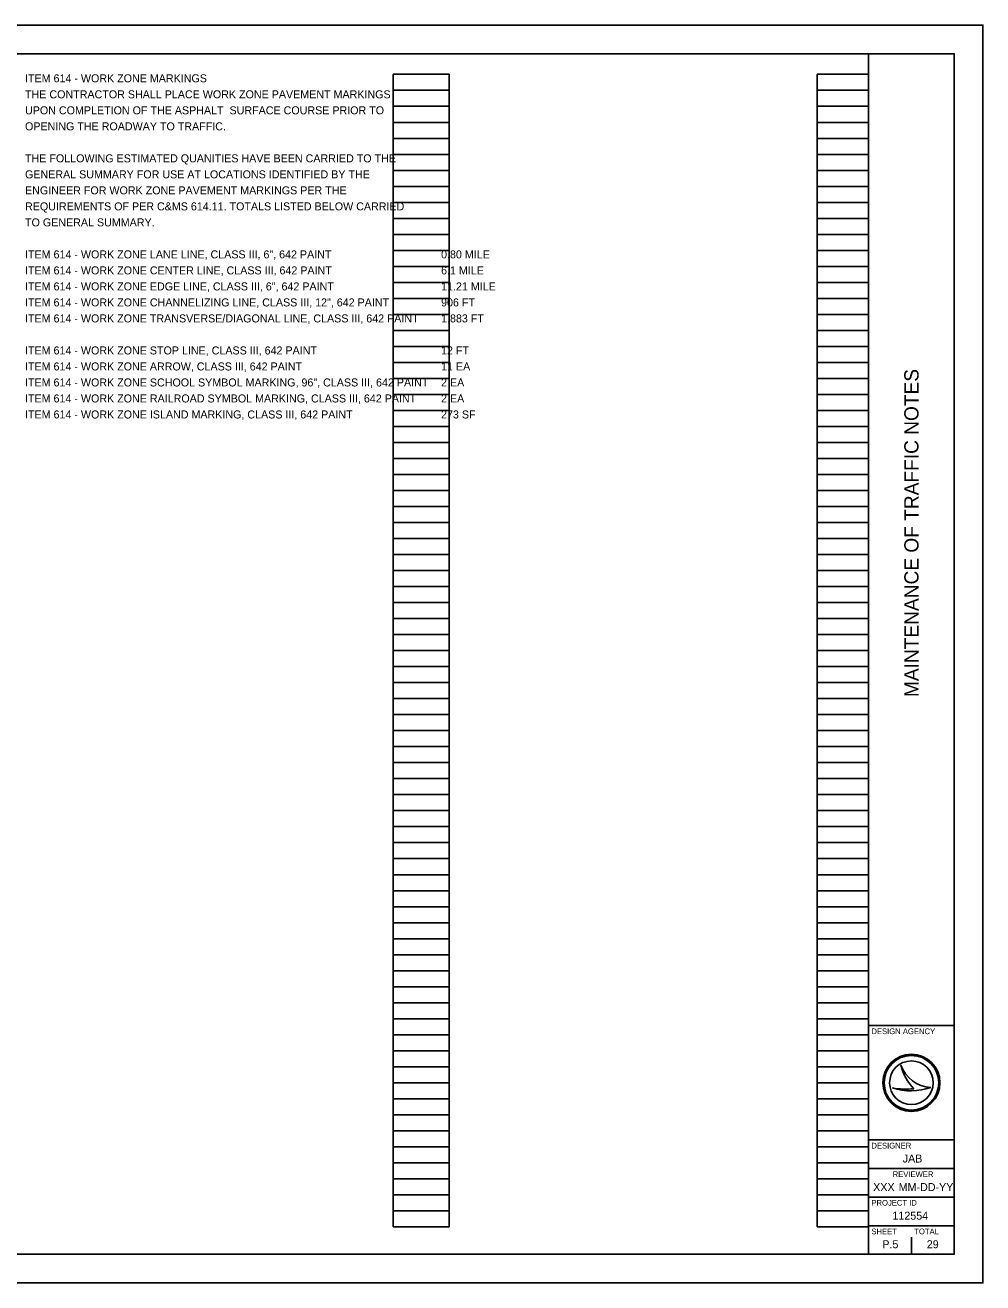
# Model space of a CAD drawing. Extents: x 0 to 34, y 0 to 22.
# Drawn here: x 17.24 to 34, y 0 to 22 of the extents above; entities that cross this region are included whole.
import ezdxf

# ---------------------------------------------------------------- set-up
doc = ezdxf.new("R2010")
doc.units = 0
for name, color, linetype in [('SH_Border', 7, 'Continuous'), ('SH_Cut_Line', 7, 'Continuous'), ('SH_Data', 7, 'Continuous'), ('SH_Text', 7, 'Continuous')]:
    doc.layers.add(name, color=color, linetype=linetype)

msp = doc.modelspace()

# ---------------------------------------------------------------- linework, layer by layer
at = {"layer": 'SH_Border'}
for p, q in [((32, 0.5), (32, 21.5)), ((32, 4.5), (33.5, 4.5)), ((32, 2.5), (33.5, 2.5)), ((32, 2), (33.5, 2)), ((32, 1.5), (33.5, 1.5)), ((32, 1), (33.5, 1))]:
    msp.add_line(p, q, dxfattribs=at)
msp.add_lwpolyline([(1.5, 21.5), (33.5, 21.5), (33.5, 0.5), (1.5, 0.5)], close=True, dxfattribs=at)
at = {"layer": 'SH_Cut_Line'}
msp.add_lwpolyline([(0, 0), (34, 0), (34, 22), (0, 22)], close=True, dxfattribs=at)
at = {"layer": 'SH_Data'}
for p, q in [((23.68, 0.98), (23.68, 21.14)), ((23.68, 21.14), (24.66, 21.14)), ((24.66, 0.98), (24.66, 21.14)), ((31.1, 0.98), (31.1, 21.14)), ((31.1, 21.14), (32, 21.14)), ((32, 0.98), (32, 21.14)), ((23.68, 20.86), (24.66, 20.86)), ((31.1, 20.86), (32, 20.86)), ((23.68, 20.58), (24.66, 20.58)), ((31.1, 20.58), (32, 20.58)), ((23.68, 20.3), (24.66, 20.3)), ((31.1, 20.3), (32, 20.3)), ((23.68, 20.02), (24.66, 20.02)), ((31.1, 20.02), (32, 20.02)), ((23.68, 19.74), (24.66, 19.74)), ((31.1, 19.74), (32, 19.74)), ((23.68, 19.46), (24.66, 19.46)), ((31.1, 19.46), (32, 19.46)), ((23.68, 19.18), (24.66, 19.18)), ((31.1, 19.18), (32, 19.18)), ((23.68, 18.9), (24.66, 18.9)), ((31.1, 18.9), (32, 18.9)), ((23.68, 18.62), (24.66, 18.62)), ((31.1, 18.62), (32, 18.62)), ((23.68, 18.34), (24.66, 18.34)), ((31.1, 18.34), (32, 18.34)), ((23.68, 18.06), (24.66, 18.06)), ((31.1, 18.06), (32, 18.06)), ((23.68, 17.78), (24.66, 17.78)), ((31.1, 17.78), (32, 17.78)), ((23.68, 17.5), (24.66, 17.5)), ((31.1, 17.5), (32, 17.5)), ((23.68, 17.22), (24.66, 17.22)), ((31.1, 17.22), (32, 17.22)), ((23.68, 16.94), (24.66, 16.94)), ((31.1, 16.94), (32, 16.94)), ((23.68, 16.66), (24.66, 16.66)), ((31.1, 16.66), (32, 16.66)), ((23.68, 16.38), (24.66, 16.38)), ((31.1, 16.38), (32, 16.38)), ((23.68, 16.1), (24.66, 16.1)), ((31.1, 16.1), (32, 16.1)), ((23.68, 15.82), (24.66, 15.82)), ((31.1, 15.82), (32, 15.82)), ((23.68, 15.54), (24.66, 15.54)), ((31.1, 15.54), (32, 15.54)), ((23.68, 15.26), (24.66, 15.26)), ((31.1, 15.26), (32, 15.26)), ((23.68, 14.98), (24.66, 14.98)), ((31.1, 14.98), (32, 14.98)), ((23.68, 14.7), (24.66, 14.7)), ((31.1, 14.7), (32, 14.7)), ((23.68, 14.42), (24.66, 14.42)), ((31.1, 14.42), (32, 14.42)), ((23.68, 14.14), (24.66, 14.14)), ((31.1, 14.14), (32, 14.14)), ((23.68, 13.86), (24.66, 13.86)), ((31.1, 13.86), (32, 13.86)), ((23.68, 13.58), (24.66, 13.58)), ((31.1, 13.58), (32, 13.58)), ((23.68, 13.3), (24.66, 13.3)), ((31.1, 13.3), (32, 13.3)), ((23.68, 13.02), (24.66, 13.02)), ((31.1, 13.02), (32, 13.02)), ((23.68, 12.74), (24.66, 12.74)), ((31.1, 12.74), (32, 12.74)), ((23.68, 12.46), (24.66, 12.46)), ((31.1, 12.46), (32, 12.46)), ((23.68, 12.18), (24.66, 12.18)), ((31.1, 12.18), (32, 12.18)), ((23.68, 11.9), (24.66, 11.9)), ((31.1, 11.9), (32, 11.9)), ((23.68, 11.62), (24.66, 11.62)), ((31.1, 11.62), (32, 11.62)), ((23.68, 11.34), (24.66, 11.34)), ((31.1, 11.34), (32, 11.34)), ((23.68, 11.06), (24.66, 11.06)), ((31.1, 11.06), (32, 11.06)), ((23.68, 10.78), (24.66, 10.78)), ((31.1, 10.78), (32, 10.78)), ((23.68, 10.5), (24.66, 10.5)), ((31.1, 10.5), (32, 10.5)), ((23.68, 10.22), (24.66, 10.22)), ((31.1, 10.22), (32, 10.22)), ((23.68, 9.94), (24.66, 9.94)), ((31.1, 9.94), (32, 9.94)), ((23.68, 9.66), (24.66, 9.66)), ((31.1, 9.66), (32, 9.66)), ((23.68, 9.38), (24.66, 9.38)), ((31.1, 9.38), (32, 9.38)), ((23.68, 9.1), (24.66, 9.1)), ((31.1, 9.1), (32, 9.1)), ((23.68, 8.82), (24.66, 8.82)), ((31.1, 8.82), (32, 8.82)), ((23.68, 8.54), (24.66, 8.54)), ((31.1, 8.54), (32, 8.54)), ((23.68, 8.26), (24.66, 8.26)), ((31.1, 8.26), (32, 8.26)), ((23.68, 7.98), (24.66, 7.98)), ((31.1, 7.98), (32, 7.98)), ((23.68, 7.7), (24.66, 7.7)), ((31.1, 7.7), (32, 7.7)), ((23.68, 7.42), (24.66, 7.42)), ((31.1, 7.42), (32, 7.42)), ((23.68, 7.14), (24.66, 7.14)), ((31.1, 7.14), (32, 7.14)), ((23.68, 6.86), (24.66, 6.86)), ((31.1, 6.86), (32, 6.86)), ((23.68, 6.58), (24.66, 6.58)), ((31.1, 6.58), (32, 6.58)), ((23.68, 6.3), (24.66, 6.3)), ((31.1, 6.3), (32, 6.3)), ((23.68, 6.02), (24.66, 6.02)), ((31.1, 6.02), (32, 6.02)), ((23.68, 5.74), (24.66, 5.74)), ((31.1, 5.74), (32, 5.74)), ((23.68, 5.46), (24.66, 5.46)), ((31.1, 5.46), (32, 5.46)), ((23.68, 5.18), (24.66, 5.18)), ((31.1, 5.18), (32, 5.18)), ((23.68, 4.9), (24.66, 4.9)), ((31.1, 4.9), (32, 4.9)), ((23.68, 4.62), (24.66, 4.62)), ((31.1, 4.62), (32, 4.62)), ((23.68, 4.34), (24.66, 4.34)), ((31.1, 4.34), (32, 4.34)), ((23.68, 4.06), (24.66, 4.06)), ((31.1, 4.06), (32, 4.06)), ((23.68, 3.78), (24.66, 3.78)), ((31.1, 3.78), (32, 3.78)), ((32.567, 3.81), (32.567, 3.81)), ((23.68, 3.5), (24.66, 3.5)), ((31.1, 3.5), (32, 3.5)), ((32.417, 3.41), (32.417, 3.41)), ((32.75, 3.5), (32.75, 3.5)), ((33.087, 3.419), (33.087, 3.419)), ((23.68, 3.22), (24.66, 3.22)), ((31.1, 3.22), (32, 3.22)), ((23.68, 2.94), (24.66, 2.94)), ((31.1, 2.94), (32, 2.94)), ((23.68, 2.66), (24.66, 2.66)), ((31.1, 2.66), (32, 2.66)), ((23.68, 2.38), (24.66, 2.38)), ((31.1, 2.38), (32, 2.38)), ((23.68, 2.1), (24.66, 2.1)), ((31.1, 2.1), (32, 2.1)), ((23.68, 1.82), (24.66, 1.82)), ((31.1, 1.82), (32, 1.82)), ((23.68, 1.54), (24.66, 1.54)), ((31.1, 1.54), (32, 1.54)), ((23.68, 1.26), (24.66, 1.26)), ((31.1, 1.26), (32, 1.26)), ((23.68, 0.98), (24.66, 0.98)), ((31.1, 0.98), (32, 0.98)), ((32.375, 0.675), (32.375, 0.675)), ((32.75, 0.5), (32.75, 0.8))]:
    msp.add_line(p, q, dxfattribs=at)
for radius in [0.5, 0.477, 0.477, 0.382]:
    msp.add_circle((32.75, 3.5), radius, dxfattribs=at)
for centre, radius, start, end in [((33.116, 3.998), 0.58, 198.9257, 198.9319), ((33.347, 3.97), 0.796, 191.6379, 191.6421), ((33.116, 3.998), 0.58, 198.9319, 267.1657), ((33.347, 3.97), 0.796, 191.6421, 226.0947), ((32.739, 4.37), 1.013, 251.4576, 290.0832), ((32.648, 4.654), 1.266, 259.4964, 259.4995), ((32.739, 4.37), 1.013, 251.4527, 251.4576), ((32.648, 4.654), 1.266, 259.4995, 276.6672)]:
    msp.add_arc(centre, radius, start, end, dxfattribs=at)

# ---------------------------------------------------------------- texts
msp.add_text('MAINTENANCE OF TRAFFIC NOTES', height=0.25, rotation=90, dxfattribs=at).set_placement((32.875, 10.247))
for s, height, p in [('DESIGN AGENCY', 0.1, (32.05, 4.35)), ('DESIGNER', 0.1, (32.05, 2.35)), ('JAB', 0.14, (32.598, 2.105)), ('REVIEWER', 0.1, (32.422, 1.85)), ('XXX', 0.14, (32.081, 1.605)), ('MM-DD-YY', 0.14, (32.527, 1.605)), ('PROJECT ID', 0.1, (32.05, 1.35)), ('112554', 0.14, (32.418, 1.105)), ('SHEET', 0.1, (32.05, 0.85)), ('TOTAL', 0.1, (32.8, 0.85)), ('P.5', 0.14, (32.241, 0.605)), ('29', 0.14, (33.019, 0.605))]:
    msp.add_text(s, height=height, dxfattribs=at).set_placement(p)
at = {"layer": 'SH_Text'}
for s, p in [('ITEM 614 - WORK ZONE MARKINGS', (17.24, 21)), ('THE CONTRACTOR SHALL PLACE WORK ZONE PAVEMENT MARKINGS ', (17.24, 20.72)), ('UPON COMPLETION OF THE ASPHALT  SURFACE COURSE PRIOR TO', (17.24, 20.44)), ('OPENING THE ROADWAY TO TRAFFIC.', (17.24, 20.16)), ('THE FOLLOWING ESTIMATED QUANITIES HAVE BEEN CARRIED TO THE ', (17.24, 19.6)), ('GENERAL SUMMARY FOR USE AT LOCATIONS IDENTIFIED BY THE ', (17.24, 19.32)), ('ENGINEER FOR WORK ZONE PAVEMENT MARKINGS PER THE ', (17.24, 19.04)), ('REQUIREMENTS OF PER C&MS 614.11. TOTALS LISTED BELOW CARRIED ', (17.24, 18.76)), ('TO GENERAL SUMMARY.', (17.24, 18.48)), ('ITEM 614 - WORK ZONE LANE LINE, CLASS III, 6", 642 PAINT', (17.24, 17.92)), ('0.80 MILE', (24.52, 17.92)), ('ITEM 614 - WORK ZONE CENTER LINE, CLASS III, 642 PAINT', (17.24, 17.64)), ('6.1 MILE', (24.52, 17.64)), ('ITEM 614 - WORK ZONE EDGE LINE, CLASS III, 6", 642 PAINT', (17.24, 17.36)), ('11.21 MILE', (24.52, 17.36)), ('ITEM 614 - WORK ZONE CHANNELIZING LINE, CLASS III, 12", 642 PAINT    ', (17.24, 17.08)), ('906 FT', (24.52, 17.08)), ('ITEM 614 - WORK ZONE TRANSVERSE/DIAGONAL LINE, CLASS III, 642 PAINT ', (17.24, 16.8)), ('1,883 FT', (24.52, 16.8)), ('ITEM 614 - WORK ZONE STOP LINE, CLASS III, 642 PAINT', (17.24, 16.24)), ('12 FT', (24.52, 16.24)), ('ITEM 614 - WORK ZONE ARROW, CLASS III, 642 PAINT', (17.24, 15.96)), ('11 EA', (24.52, 15.96)), ('ITEM 614 - WORK ZONE SCHOOL SYMBOL MARKING, 96", CLASS III, 642 PAINT      ', (17.24, 15.68)), ('2 EA', (24.52, 15.68)), ('ITEM 614 - WORK ZONE RAILROAD SYMBOL MARKING, CLASS III, 642 PAINT', (17.24, 15.4)), ('2 EA', (24.52, 15.4)), ('ITEM 614 - WORK ZONE ISLAND MARKING, CLASS III, 642 PAINT', (17.24, 15.12)), ('273 SF', (24.52, 15.12))]:
    msp.add_text(s, height=0.14, dxfattribs=at).set_placement(p)

doc.saveas('drawing.dxf')
